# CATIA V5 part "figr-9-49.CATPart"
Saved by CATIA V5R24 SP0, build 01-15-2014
Part number: Part1
Bounding box of the stored display mesh (mm): x -53.48 to 62.241, y -50 to 50, z -57.709 to 133.109
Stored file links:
  D:\KAVITA\CATIA V5-6R2014 Project_ Kavita\CATIA V5-6R2014_partfiles\Partfiles\c09_catia_v5-6r2014_prt\figr-9-49.CATPart
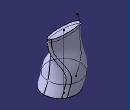
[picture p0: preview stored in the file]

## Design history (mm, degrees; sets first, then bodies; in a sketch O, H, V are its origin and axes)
Body1 (main body)
  Plane1: type Offset, RefPlane xy-plane, Offset 103
  Sketch1 on Plane1, origin (0, 0, 103), H (1, 0, 0), V (0, 1, 0)
    ellipse A1 centre (0, 0) semi-axes 50, 13.2069 rotation 0
    point P1 (50, 0)
    "Radius" A1 = 50
    coincidence: P1 H, A1 P1
  Extremum1: Reference Sketch1, Direction (1, 2, 3)
  Sketch2 on xy-plane, origin (0, 0, 0), H (1, 0, 0), V (0, 1, 0)
    circle A1 centre (0, 0) radius 50
    radius A1 = 50
  Extremum2: Reference Sketch2, Direction (1, 2, 3)
  Sketch3 on zx-plane, origin (0, 0, 0), H (-1, 0, 0), V (0, 0, 1)
    spline S1 through (37.7591, -31.0289) (41.8235, -21.251) (50, 0) (49.8084, 85.7657) (50, 103) (41.6255, 133.1089)
    reference projected line E1 (-50, 103) -> (50, 103) from Sketch1.A1
    point P1 (50, 0)
    point P2 (50, 103)
    distance V P1 = 50
    distance P2 V = 50
    coincidence: P1 H, P2 E1
  Sketch4 on zx-plane, origin (0, 0, 0), H (-1, 0, 0), V (0, 0, 1)
    line L1 (0, 111.062) -> (0, -57.7094)
    point P1 (0, 111.062)
    coincidence: P1 V
    vertical: L1 V
  Loft1: solid, Sections (Sketch1; Sketch2), Spine Sketch4, Guides Sketch3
